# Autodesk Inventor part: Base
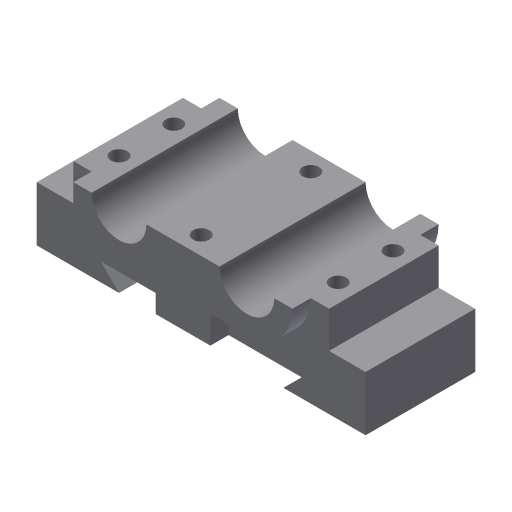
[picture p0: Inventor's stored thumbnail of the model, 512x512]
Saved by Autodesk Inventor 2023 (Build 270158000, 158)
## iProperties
Created: 2002-02
Part Number: Base
Document SubType Name: Modeling
Designer: ***
Density: 1 g/cm^3
Material: Generic
Appearance: Default
Control State: 0
Master: False
Checked Out: False
Shininess: 77.0
Length Units: 11269
Angle Units: 11279
Time Units: 11290
Mass Units: 11283
Length Display Precision: 3
Angle Display Precision: 2
Density: 0.0
Volumn: 0.0
Area: 0.0
PropertySet Name: Model Information
Author: ***
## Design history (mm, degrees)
sketch "Sketch2"
  geometry: L1 (-10.066, -1.263)-(24.934, -1.263); L2 (37.434, 11.237)-(32.434, 11.237); L3 (17.434, 11.237)-(-2.566, 11.237); L4 (-17.566, 11.237)-(-22.566, 11.237); A1 r 12.5 centre (-10.066, 11.237) between (-22.566, 11.237) and (-10.066, -1.263); A2 r 12.5 centre (24.934, 11.237) between (24.934, -1.263) and (37.434, 11.237); A3 r 7.5 centre (24.934, 11.237) between (17.434, 11.237) and (32.434, 11.237); A4 r 7.5 centre (-10.066, 11.237) between (-17.566, 11.237) and (-2.566, 11.237)
  constraints: 8 end point, 8 point on circle, 4 centre point, 3 horizontal, 3 parallel, 2 coincident, 2 equal radius, 2 tangent
  dimensions: "d0" = 12.5 radius of A1; "d1" = 7.5 radius of A4; "d2" = 35 distance of A1.centre A2.centre; "d3" = 12.5 distance between parallel lines of L3 L1
extrude "Extrusion1" new body sketch "Sketch2" stored distance "d4" = 40; taper "d5" = 0 deg
sketch "Sketch4"
  geometry: L1 (-27.566, 1.237)-(-37.566, 1.237); L2 (-37.566, 1.237)-(-37.566, -13.763); L3 (-37.566, -13.763)-(-15.066, -13.763); L4 (-15.066, -13.763)-(-20.066, -8.763); L5 (-20.066, -8.763)-(34.934, -8.763); L6 (34.934, -8.763)-(29.934, -13.763); L7 (29.934, -13.763)-(52.434, -13.763); L8 (52.434, -13.763)-(52.434, 1.237); L9 (52.434, 1.237)-(42.434, 1.237); L10 (24.934, -1.263)-(-10.066, -1.263); L11 (-17.566, 11.237)-(-22.566, 11.237) reference; L12 (37.434, 11.237)-(32.434, 11.237) reference; L13 (-22.566, 11.237)-(-27.566, 11.237); L14 (-27.566, 11.237)-(-27.566, 1.237); L15 (37.434, 11.237)-(42.434, 11.237); L16 (42.434, 11.237)-(42.434, 1.237); A1 r 12.5 centre (24.934, 11.237) between (24.934, -1.263) and (37.434, 11.237); A2 r 12.5 centre (-10.066, 11.237) between (-22.566, 11.237) and (-10.066, -1.263); A3 r 12.5 centre (24.934, 11.237) between (24.934, -1.263) and (37.434, 11.237) reference; A4 r 12.5 centre (-10.066, 11.237) between (-22.566, 11.237) and (-10.066, -1.263) reference
  constraints: 28 end point, 6 perpendicular, 5 equal length, 4 concentric, 4 parallel, 4 point on circle, 2 centre point, 2 collinear, 1 tangent
  dimensions: "d12" = 15 distance of L1.end L2.end; "d13" = 25 distance from line of L3 L11.end; "d14" = 90 distance between parallel lines of L2 L8; "d15" = 5 distance between parallel lines of L5 L7; "d16" = 22.5 distance of L2.end L3.end; "d24" = 5 distance of L12.start L15.end; "d25" = 15 distance from line of L8 L12.start
extrude "Extrusion3" join sketch "Sketch4" stored distance "d17" = 30; taper "d18" = 0 deg
sketch "Sketch5"
  geometry: L1 (-14.934, -1.263)-(0.066, -1.263); L2 (0.066, -1.263)-(0.066, -8.763); L3 (0.066, -8.763)-(-14.934, -8.763); L4 (-14.934, -8.763)-(-14.934, -1.263); L5 (10.066, -1.263)-(-24.934, -1.263) reference; 1 further point
  constraints: 8 end point, 2 parallel, 1 collinear, 1 horizontal, 1 perpendicular
  dimensions: "d19" = 7.5 distance of L1.end L2.end; "d20" = 15 distance of L2.end L3.end; "d21" = 15 distance from line of point (-29.934, -13.763) L4
extrude "Extrusion4" join sketch "Sketch5" distance "d22" = 40; taper "d23" = 0 deg
sketch "Sketch6"
  geometry: L1 (-5, -35)-(0, -35) reference; L2 (-5, -35)-(-5, -5) reference; 1 further point
  dimensions: "d26" = 7.5 distance from line of L1 point (0, -27.5); "d27" = 5 distance from line of L2 point (0, -27.5)
hole "Hole1" sketch "Sketch6" at (0, -27.5) diameter "d28" = 4.5; stored, may be unused: countersink angle "d32" = 82 deg, drill point angle "d34" = 0 deg; dims "d29" = 6, "d30" = 4, "d31" = 2, "d33" = 15
pattern_linear "Rectangular Pattern1" dims "d37" = 60, "d40" = 15
sketch "Sketch7"
  geometry: L1 (-20, -40)-(-20, -35) reference; L2 (0, -40)-(20, -40) reference; 1 further point
  dimensions: "d41" = 30 distance from line of L1 point (10, -35); "d42" = 5 distance from line of L2 point (10, -35)
hole "Hole2" sketch "Sketch7" at (10, -35) diameter "d43" = 4.5; stored, may be unused: countersink angle "d47" = 82 deg, drill point angle "d49" = 0 deg; dims "d44" = 6, "d45" = 4, "d46" = 2, "d48" = 15
pattern_linear "Rectangular Pattern2" dims "d52" = 30
body "Solid1"
